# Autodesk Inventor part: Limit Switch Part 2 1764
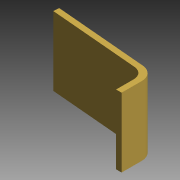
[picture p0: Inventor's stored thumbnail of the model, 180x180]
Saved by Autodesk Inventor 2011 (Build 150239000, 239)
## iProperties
Shininess: 0.0
Created: 2002-01
Part Number: Limit Switch Part 2 1764
Document SubType Name: Modeling
Density: 1 g/cm^3
Density: 0.0
Volumn: 0.0
Area: 0.0
PropertySet Name: Model Information
Control State: 0
Master: False
Checked Out: False
Author: Administrator
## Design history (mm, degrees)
node "Base1"
body "Solid1"
